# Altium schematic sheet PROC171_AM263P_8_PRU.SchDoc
size 431 x 279 mm; Date: Not shown in title block; ApprovedBy: Not shown in title block; CheckedBy: Not shown in title block; Author: Not shown in title block; CompanyName: Not shown in title block; Engineer: Not shown in title block; Organization: Not shown in title block; Address1: Not shown in title block; Address2: Not shown in title block; Address3: Not shown in title block; Address4: Not shown in title block; DocumentNumber: 12; Revision: Use project parameter SCH_Rev; SheetNumber: 12; SheetTotal: 26; PageSetup: Record=PageOptions¦CenterHorizontal=True¦CenterVertical=True¦PrintScale=1.00¦XCorrection=1.00¦YCorrection=1.00¦PrintKind=0¦BorderSize=5000000¦LeftOffset=0¦BottomOffset=0¦Orientation=2¦PaperLength=1000¦PaperWidth=1000¦Scale=100¦PaperSource=15¦PrintQuality=600¦MediaType=1¦DitherType=10¦PaperKind=Letter¦PrintScaleMode=1
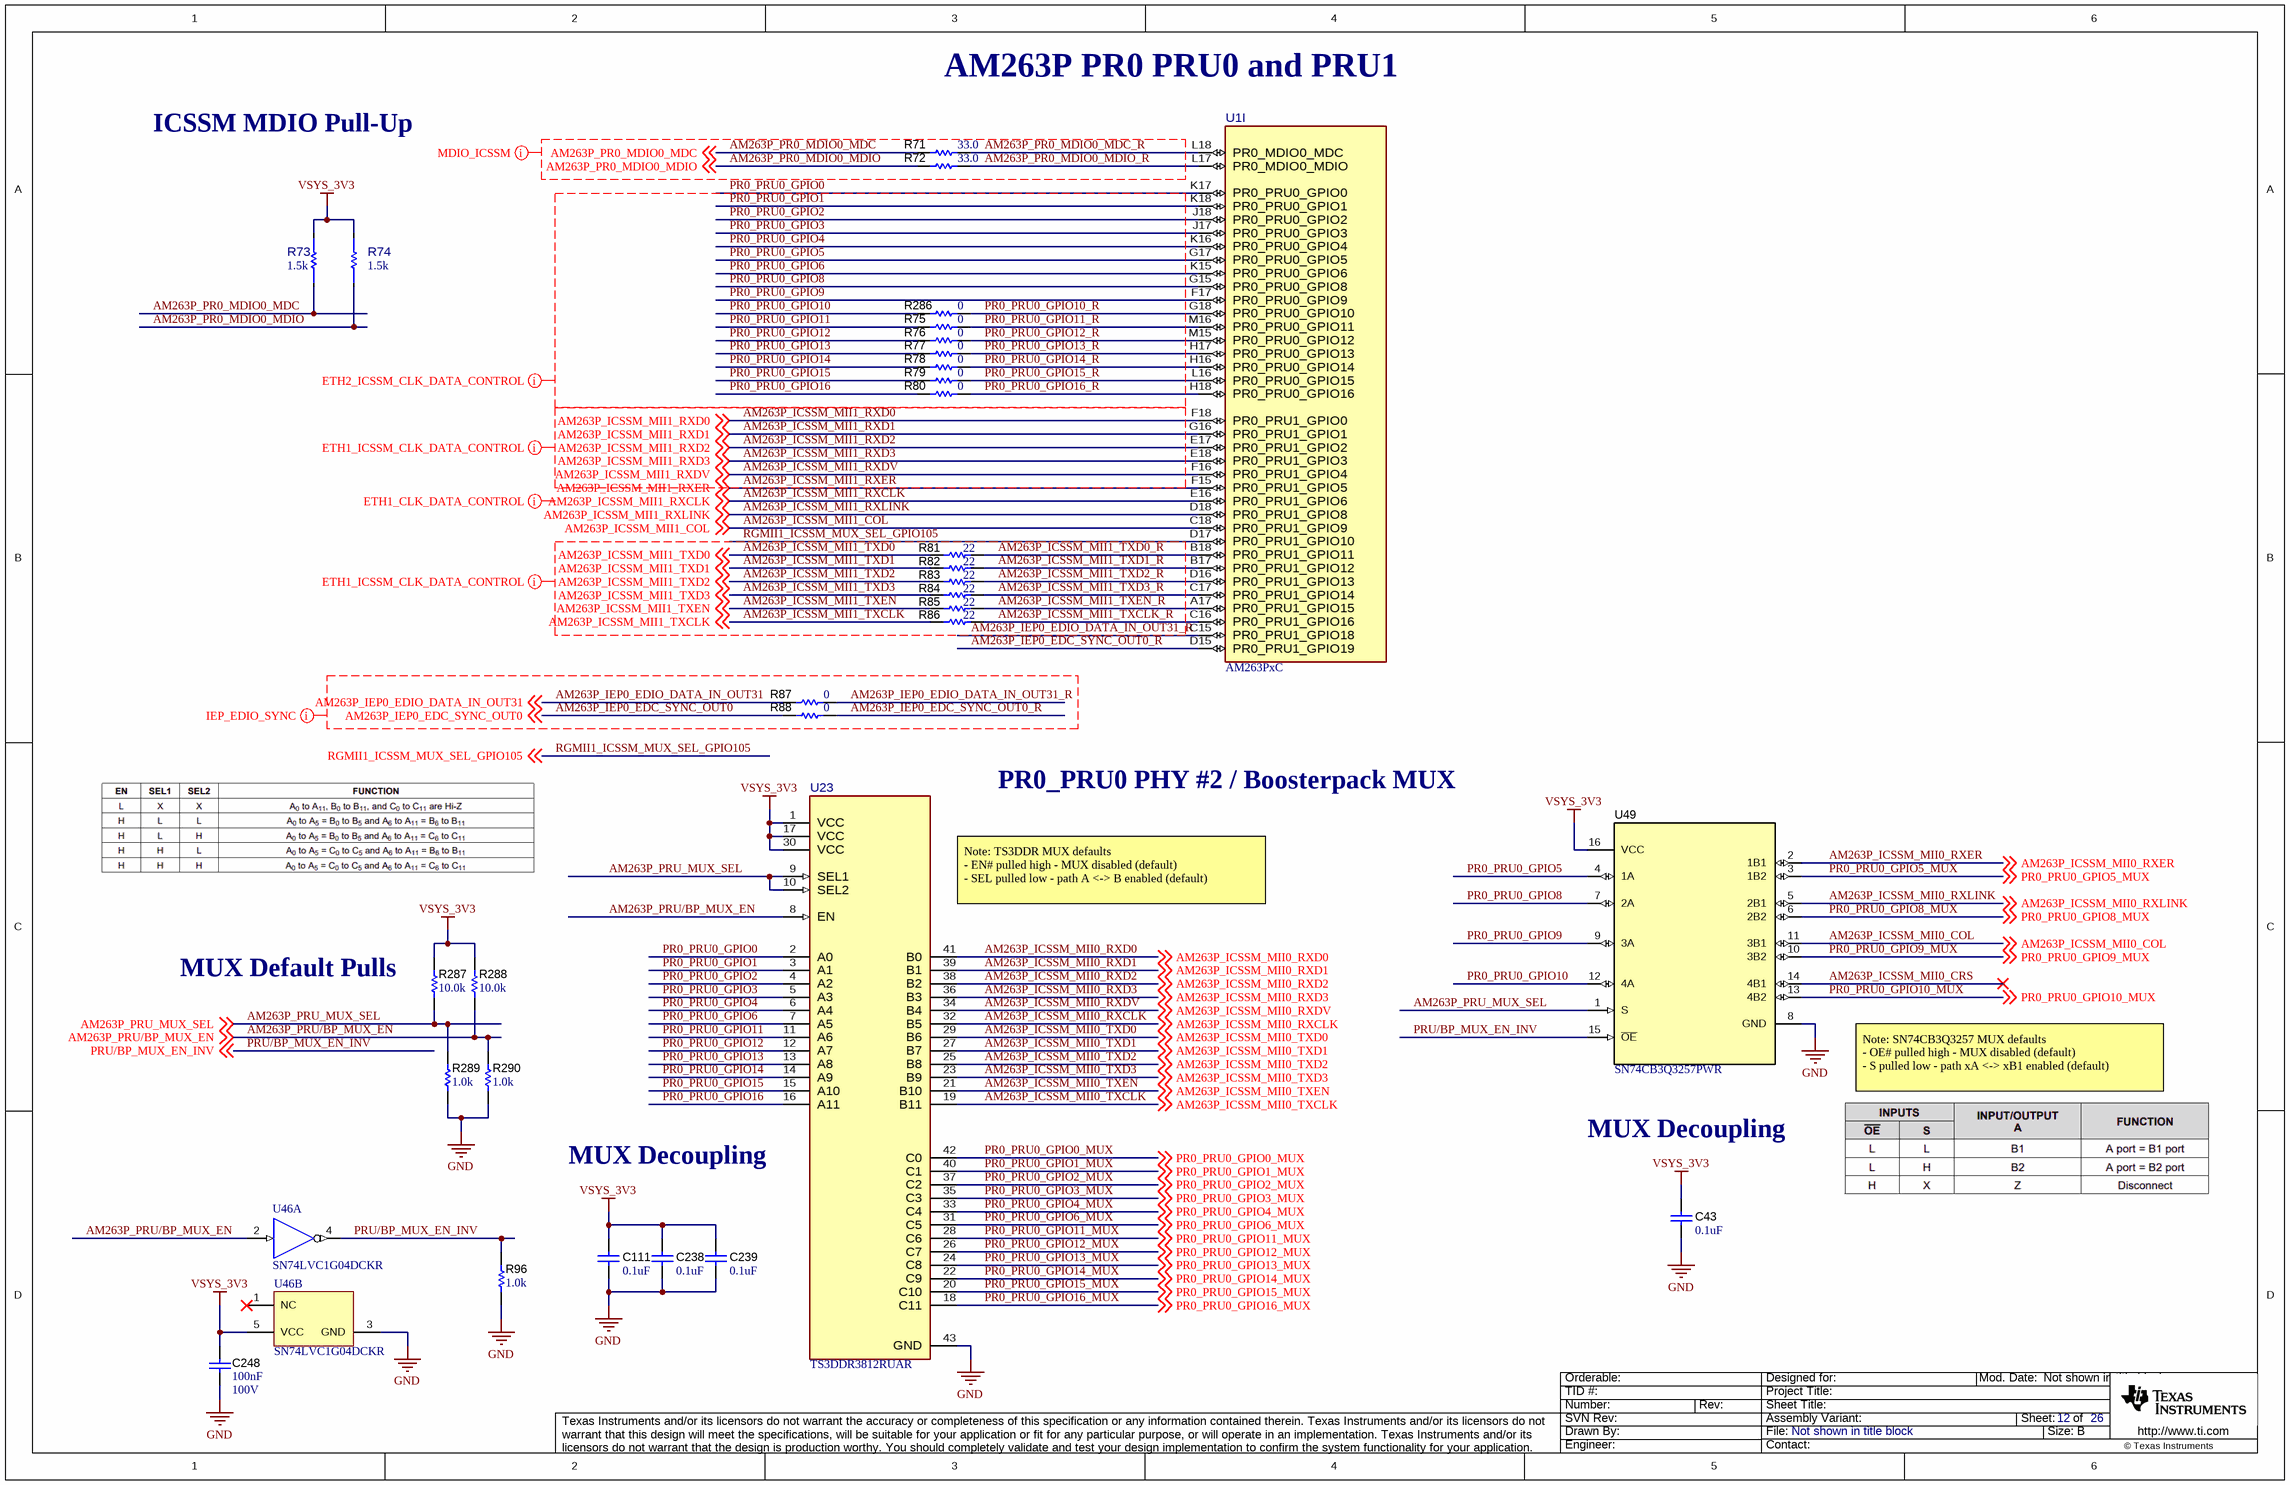
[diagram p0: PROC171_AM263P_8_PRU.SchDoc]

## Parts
C43  ValueDisplayed: 0.1uF  [0402]  (hidden comment: GRM155R71E104KE14D)
C111  ValueDisplayed: 0.1uF  [0402]  (hidden comment: GRM155R71E104KE14D)
C238  ValueDisplayed: 0.1uF  [0402]  (hidden comment: GRM155R71E104KE14D)
C239  ValueDisplayed: 0.1uF  [0402]  (hidden comment: GRM155R71E104KE14D)
C248  Cap_F: 100nF  VDC_V: 100V  [0603]  (hidden comment: GRM188R72A104KA35D)
R71  ValueDisplayed: 33.0  [0402L]  (hidden comment: ERJ-2RKF33R0X)
R72  ValueDisplayed: 33.0  [0402L]  (hidden comment: ERJ-2RKF33R0X)
R73  value 1.5k  [FP-ERJ-2GEJ152X_0402-MFG]  (hidden comment: ERJ-2GEJ152X)
R74  value 1.5k  [FP-ERJ-2GEJ152X_0402-MFG]  (hidden comment: ERJ-2GEJ152X)
R75  value 0  [0402L]  (hidden comment: ERJ-2GE0R00X)
R76  value 0  [0402L]  (hidden comment: ERJ-2GE0R00X)
R77  value 0  [0402L]  (hidden comment: ERJ-2GE0R00X)
R78  value 0  [0402L]  (hidden comment: ERJ-2GE0R00X)
R79  value 0  [0402L]  (hidden comment: ERJ-2GE0R00X)
R80  value 0  [0402L]  (hidden comment: ERJ-2GE0R00X)
R81  ValueDisplayed: 22  [0402]  (hidden comment: CRCW040222R0JNED)
R82  ValueDisplayed: 22  [0402]  (hidden comment: CRCW040222R0JNED)
R83  ValueDisplayed: 22  [0402]  (hidden comment: CRCW040222R0JNED)
R84  ValueDisplayed: 22  [0402]  (hidden comment: CRCW040222R0JNED)
R85  ValueDisplayed: 22  [0402]  (hidden comment: CRCW040222R0JNED)
R86  ValueDisplayed: 22  [0402]  (hidden comment: CRCW040222R0JNED)
R87  value 0  [0402L]  (hidden comment: ERJ-2GE0R00X)
R88  value 0  [0402L]  (hidden comment: ERJ-2GE0R00X)
R96  ValueDisplayed: 1.0k  [0402]  (hidden comment: ERJ-2GEJ102X)
R286  value 0  [0402L]  (hidden comment: ERJ-2GE0R00X)
R287  ValueDisplayed: 10.0k  [0402]  (hidden comment: ERJ-2RKF1002X)
R288  ValueDisplayed: 10.0k  [0402]  (hidden comment: ERJ-2RKF1002X)
R289  ValueDisplayed: 1.0k  [0402]  (hidden comment: ERJ-2GEJ102X)
R290  ValueDisplayed: 1.0k  [0402]  (hidden comment: ERJ-2GEJ102X)
U1  AM263PxC  [ZCZ0324A-MFG]  (part I of 13)
U23  TS3DDR3812RUAR  [RUA0042A-MFG]
U46  SN74LVC1G04DCKR  [DCK0005A_N]  (parts A,B of 2)
U49  SN74CB3Q3257PWR  [PW0016A_L]

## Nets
GND: C43.1 C111.1 C238.1 C239.1 C248.2 R96.1 R289.1 R290.1 U23.43(GND) U46.3(GND) U49.8(GND)
VSYS_3V3: C43.2 C111.2 C238.2 C239.2 C248.1 R73.2 R74.2 R287.1 R288.1 U23.1(VCC) U23.17(VCC) U23.30(VCC) U46.5(VCC) U49.16(VCC)
AM263P_ICSSM_MII0_COL: U49.11(3B1) ; off-sheet AM263P_ICSSM_MII0_COL
AM263P_ICSSM_MII0_CRS: U49.14(4B1)
AM263P_ICSSM_MII0_RXCLK: U23.32(B5) ; off-sheet AM263P_ICSSM_MII0_RXCLK
AM263P_ICSSM_MII0_RXD0: U23.41(B0) ; off-sheet AM263P_ICSSM_MII0_RXD0
AM263P_ICSSM_MII0_RXD1: U23.39(B1) ; off-sheet AM263P_ICSSM_MII0_RXD1
AM263P_ICSSM_MII0_RXD2: U23.38(B2) ; off-sheet AM263P_ICSSM_MII0_RXD2
AM263P_ICSSM_MII0_RXD3: U23.36(B3) ; off-sheet AM263P_ICSSM_MII0_RXD3
AM263P_ICSSM_MII0_RXDV: U23.34(B4) ; off-sheet AM263P_ICSSM_MII0_RXDV
AM263P_ICSSM_MII0_RXER: U49.2(1B1) ; off-sheet AM263P_ICSSM_MII0_RXER
AM263P_ICSSM_MII0_RXLINK: U49.5(2B1) ; off-sheet AM263P_ICSSM_MII0_RXLINK
AM263P_ICSSM_MII0_TXCLK: U23.19(B11) ; off-sheet AM263P_ICSSM_MII0_TXCLK
AM263P_ICSSM_MII0_TXD0: U23.29(B6) ; off-sheet AM263P_ICSSM_MII0_TXD0
AM263P_ICSSM_MII0_TXD1: U23.27(B7) ; off-sheet AM263P_ICSSM_MII0_TXD1
AM263P_ICSSM_MII0_TXD2: U23.25(B8) ; off-sheet AM263P_ICSSM_MII0_TXD2
AM263P_ICSSM_MII0_TXD3: U23.23(B9) ; off-sheet AM263P_ICSSM_MII0_TXD3
AM263P_ICSSM_MII0_TXEN: U23.21(B10) ; off-sheet AM263P_ICSSM_MII0_TXEN
AM263P_ICSSM_MII1_COL: U1.C18(PR0_PRU1_GPIO9) ; off-sheet AM263P_ICSSM_MII1_COL
AM263P_ICSSM_MII1_RXCLK: U1.E16(PR0_PRU1_GPIO6) ; off-sheet AM263P_ICSSM_MII1_RXCLK
AM263P_ICSSM_MII1_RXD0: U1.F18(PR0_PRU1_GPIO0) ; off-sheet AM263P_ICSSM_MII1_RXD0
AM263P_ICSSM_MII1_RXD1: U1.G16(PR0_PRU1_GPIO1) ; off-sheet AM263P_ICSSM_MII1_RXD1
AM263P_ICSSM_MII1_RXD2: U1.E17(PR0_PRU1_GPIO2) ; off-sheet AM263P_ICSSM_MII1_RXD2
AM263P_ICSSM_MII1_RXD3: U1.E18(PR0_PRU1_GPIO3) ; off-sheet AM263P_ICSSM_MII1_RXD3
AM263P_ICSSM_MII1_RXDV: U1.F16(PR0_PRU1_GPIO4) ; off-sheet AM263P_ICSSM_MII1_RXDV
AM263P_ICSSM_MII1_RXER: U1.F15(PR0_PRU1_GPIO5) ; off-sheet AM263P_ICSSM_MII1_RXER
AM263P_ICSSM_MII1_RXLINK: U1.D18(PR0_PRU1_GPIO8) ; off-sheet AM263P_ICSSM_MII1_RXLINK
AM263P_ICSSM_MII1_TXCLK: R86.1 ; off-sheet AM263P_ICSSM_MII1_TXCLK
AM263P_ICSSM_MII1_TXCLK_R: R86.2 U1.C16(PR0_PRU1_GPIO16)
AM263P_ICSSM_MII1_TXD0: R81.1 ; off-sheet AM263P_ICSSM_MII1_TXD0
AM263P_ICSSM_MII1_TXD0_R: R81.2 U1.B18(PR0_PRU1_GPIO11)
AM263P_ICSSM_MII1_TXD1: R82.1 ; off-sheet AM263P_ICSSM_MII1_TXD1
AM263P_ICSSM_MII1_TXD1_R: R82.2 U1.B17(PR0_PRU1_GPIO12)
AM263P_ICSSM_MII1_TXD2: R83.1 ; off-sheet AM263P_ICSSM_MII1_TXD2
AM263P_ICSSM_MII1_TXD2_R: R83.2 U1.D16(PR0_PRU1_GPIO13)
AM263P_ICSSM_MII1_TXD3: R84.1 ; off-sheet AM263P_ICSSM_MII1_TXD3
AM263P_ICSSM_MII1_TXD3_R: R84.2 U1.C17(PR0_PRU1_GPIO14)
AM263P_ICSSM_MII1_TXEN: R85.1 ; off-sheet AM263P_ICSSM_MII1_TXEN
AM263P_ICSSM_MII1_TXEN_R: R85.2 U1.A17(PR0_PRU1_GPIO15)
AM263P_IEP0_EDC_SYNC_OUT0: R88.1 ; off-sheet AM263P_IEP0_EDC_SYNC_OUT0
AM263P_IEP0_EDC_SYNC_OUT0_R: R88.2 U1.D15(PR0_PRU1_GPIO19)
AM263P_IEP0_EDIO_DATA_IN_OUT31: R87.1 ; off-sheet AM263P_IEP0_EDIO_DATA_IN_OUT31
AM263P_IEP0_EDIO_DATA_IN_OUT31_R: R87.2 U1.C15(PR0_PRU1_GPIO18)
AM263P_PR0_MDIO0_MDC: R71.1 R73.1 ; off-sheet AM263P_PR0_MDIO0_MDC
AM263P_PR0_MDIO0_MDC_R: R71.2 U1.L18(PR0_MDIO0_MDC)
AM263P_PR0_MDIO0_MDIO: R72.1 R74.1 ; off-sheet AM263P_PR0_MDIO0_MDIO
AM263P_PR0_MDIO0_MDIO_R: R72.2 U1.L17(PR0_MDIO0_MDIO)
AM263P_PRU/BP_MUX_EN: R288.2 R290.2 U23.8(EN) U46.2(A) ; off-sheet AM263P_PRU/BP_MUX_EN
AM263P_PRU_MUX_SEL: R287.2 R289.2 U23.9(SEL1) U23.10(SEL2) U49.1(S) ; off-sheet AM263P_PRU_MUX_SEL
PR0_PRU0_GPIO0: U1.K17(PR0_PRU0_GPIO0) U23.2(A0)
PR0_PRU0_GPIO0_MUX: U23.42(C0) ; off-sheet PR0_PRU0_GPIO0_MUX
PR0_PRU0_GPIO1: U1.K18(PR0_PRU0_GPIO1) U23.3(A1)
PR0_PRU0_GPIO1_MUX: U23.40(C1) ; off-sheet PR0_PRU0_GPIO1_MUX
PR0_PRU0_GPIO2: U1.J18(PR0_PRU0_GPIO2) U23.4(A2)
PR0_PRU0_GPIO2_MUX: U23.37(C2) ; off-sheet PR0_PRU0_GPIO2_MUX
PR0_PRU0_GPIO3: U1.J17(PR0_PRU0_GPIO3) U23.5(A3)
PR0_PRU0_GPIO3_MUX: U23.35(C3) ; off-sheet PR0_PRU0_GPIO3_MUX
PR0_PRU0_GPIO4: U1.K16(PR0_PRU0_GPIO4) U23.6(A4)
PR0_PRU0_GPIO4_MUX: U23.33(C4) ; off-sheet PR0_PRU0_GPIO4_MUX
PR0_PRU0_GPIO5: U1.G17(PR0_PRU0_GPIO5) U49.4(1A)
PR0_PRU0_GPIO5_MUX: U49.3(1B2) ; off-sheet PR0_PRU0_GPIO5_MUX
PR0_PRU0_GPIO6: U1.K15(PR0_PRU0_GPIO6) U23.7(A5)
PR0_PRU0_GPIO6_MUX: U23.31(C5) ; off-sheet PR0_PRU0_GPIO6_MUX
PR0_PRU0_GPIO8: U1.G15(PR0_PRU0_GPIO8) U49.7(2A)
PR0_PRU0_GPIO8_MUX: U49.6(2B2) ; off-sheet PR0_PRU0_GPIO8_MUX
PR0_PRU0_GPIO9: U1.F17(PR0_PRU0_GPIO9) U49.9(3A)
PR0_PRU0_GPIO9_MUX: U49.10(3B2) ; off-sheet PR0_PRU0_GPIO9_MUX
PR0_PRU0_GPIO10: R286.1 U49.12(4A)
PR0_PRU0_GPIO10_MUX: U49.13(4B2) ; off-sheet PR0_PRU0_GPIO10_MUX
PR0_PRU0_GPIO10_R: R286.2 U1.G18(PR0_PRU0_GPIO10)
PR0_PRU0_GPIO11: R75.1 U23.11(A6)
PR0_PRU0_GPIO11_MUX: U23.28(C6) ; off-sheet PR0_PRU0_GPIO11_MUX
PR0_PRU0_GPIO11_R: R75.2 U1.M16(PR0_PRU0_GPIO11)
PR0_PRU0_GPIO12: R76.1 U23.12(A7)
PR0_PRU0_GPIO12_MUX: U23.26(C7) ; off-sheet PR0_PRU0_GPIO12_MUX
PR0_PRU0_GPIO12_R: R76.2 U1.M15(PR0_PRU0_GPIO12)
PR0_PRU0_GPIO13: R77.1 U23.13(A8)
PR0_PRU0_GPIO13_MUX: U23.24(C8) ; off-sheet PR0_PRU0_GPIO13_MUX
PR0_PRU0_GPIO13_R: R77.2 U1.H17(PR0_PRU0_GPIO13)
PR0_PRU0_GPIO14: R78.1 U23.14(A9)
PR0_PRU0_GPIO14_MUX: U23.22(C9) ; off-sheet PR0_PRU0_GPIO14_MUX
PR0_PRU0_GPIO14_R: R78.2 U1.H16(PR0_PRU0_GPIO14)
PR0_PRU0_GPIO15: R79.1 U23.15(A10)
PR0_PRU0_GPIO15_MUX: U23.20(C10) ; off-sheet PR0_PRU0_GPIO15_MUX
PR0_PRU0_GPIO15_R: R79.2 U1.L16(PR0_PRU0_GPIO15)
PR0_PRU0_GPIO16: R80.1 U23.16(A11)
PR0_PRU0_GPIO16_MUX: U23.18(C11) ; off-sheet PR0_PRU0_GPIO16_MUX
PR0_PRU0_GPIO16_R: R80.2 U1.H18(PR0_PRU0_GPIO16)
PRU/BP_MUX_EN_INV: R96.2 U46.4(Y) U49.15(~{OE}) ; off-sheet PRU/BP_MUX_EN_INV
RGMII1_ICSSM_MUX_SEL_GPIO105: U1.D17(PR0_PRU1_GPIO10) ; off-sheet RGMII1_ICSSM_MUX_SEL_GPIO105

Not connected (* = marked no-connect by the designer): U46 1(NC)*

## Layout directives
mark named IEP_EDIO_SYNC: AM263P_IEP0_EDC_SYNC_OUT0, AM263P_IEP0_EDC_SYNC_OUT0_R, AM263P_IEP0_EDIO_DATA_IN_OUT31, AM263P_IEP0_EDIO_DATA_IN_OUT31_R
mark named ETH2_ICSSM_CLK_DATA_CONTROL: PR0_PRU0_GPIO0, PR0_PRU0_GPIO1, PR0_PRU0_GPIO2, PR0_PRU0_GPIO3, PR0_PRU0_GPIO4, PR0_PRU0_GPIO5, PR0_PRU0_GPIO6, PR0_PRU0_GPIO8, PR0_PRU0_GPIO9, PR0_PRU0_GPIO10, PR0_PRU0_GPIO10_R, PR0_PRU0_GPIO11, PR0_PRU0_GPIO11_R, PR0_PRU0_GPIO12, PR0_PRU0_GPIO12_R, PR0_PRU0_GPIO13, PR0_PRU0_GPIO13_R, PR0_PRU0_GPIO14, PR0_PRU0_GPIO14_R, PR0_PRU0_GPIO15, PR0_PRU0_GPIO15_R, PR0_PRU0_GPIO16, PR0_PRU0_GPIO16_R
mark named ETH1_ICSSM_CLK_DATA_CONTROL: AM263P_ICSSM_MII1_RXD0, AM263P_ICSSM_MII1_RXD1, AM263P_ICSSM_MII1_RXD2, AM263P_ICSSM_MII1_RXD3, AM263P_ICSSM_MII1_RXDV, AM263P_ICSSM_MII1_RXER, AM263P_ICSSM_MII1_TXCLK, AM263P_ICSSM_MII1_TXCLK_R, AM263P_ICSSM_MII1_TXD0, AM263P_ICSSM_MII1_TXD0_R, AM263P_ICSSM_MII1_TXD1, AM263P_ICSSM_MII1_TXD1_R, AM263P_ICSSM_MII1_TXD2, AM263P_ICSSM_MII1_TXD2_R, AM263P_ICSSM_MII1_TXD3, AM263P_ICSSM_MII1_TXD3_R, AM263P_ICSSM_MII1_TXEN, AM263P_ICSSM_MII1_TXEN_R, AM263P_IEP0_EDIO_DATA_IN_OUT31_R, RGMII1_ICSSM_MUX_SEL_GPIO105
mark named MDIO_ICSSM: AM263P_PR0_MDIO0_MDC, AM263P_PR0_MDIO0_MDC_R, AM263P_PR0_MDIO0_MDIO, AM263P_PR0_MDIO0_MDIO_R
mark named ETH1_CLK_DATA_CONTROL: (no net found under the mark)

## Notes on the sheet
- AM263P PR0 PRU0 and PRU1
- ICSSM MDIO Pull-Up
- PR0_PRU0 PHY #2 / Boosterpack MUX
- (near U23) Note: TS3DDR MUX defaults
  - EN# pulled high - MUX disabled (default)
  - SEL pulled low - path A <-> B enabled (default)
- (near R287) MUX Default Pulls
- Note: SN74CB3Q3257 MUX defaults
  - OE# pulled high - MUX disabled (default)
  - S pulled low - path xA <-> xB1 enabled (default)
- MUX Decoupling

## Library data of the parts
C43 C111 C238 C239 = CMP-0006659-2: CAP, CERM, 0.1 uF, 25 V, +/- 10%, X7R, 0402; Manufacturer: MuRata; TaMin_C: -55°C; Polarized: N; SizeAreaWB_mm2: 3; U/M: EA; Value: 0.1uF; TaMax_C: 125°C; SizeZ_mm: 0.6; SizeX_mm: 1; SizeY_mm: 0.5; Value2: 25V; Cap_F: 100nF; AEC Category: Q200; Value1: Unknown
C248 = CMP-0007469-4: CAP, CERM, 0.1 uF, 100 V, +/- 10%, X7R, 0603; Manufacturer: MuRata; TaMin_C: -55°C; Polarized: N; SizeAreaWB_mm2: 4.68; Value1: Unknown; U/M: EA; Value: 0.1uF; TaMax_C: 125°C; SizeZ_mm: 1; SizeX_mm: 1.6; SizeY_mm: 0.8; SizeArea_mm2: 1.28; AEC Category: Q200
R71 R72 = CMP-0026696-1: RES, 33.0, 1%, 0.1 W, 0402; Manufacturer: Panasonic; Power_W: 100mW; TempCo: 100 ppm/C; Value_Code: 33R0; U/M: EA; Value: 33.0; Res_ohm: 33; SizeX_mm: 1; SizeY_mm: 0.5; SizeZ_mm: 0.6; Value2: 0.1W; VDC_V: 50V; AEC Category: Q200
R73 R74 = CMP-0042990-1: Res Thick Film 0402 1.5K Ohm 5% 1/10W ±200ppm/°C Molded SMD Punched Carrier T/R; Manufacturer: Panasonic; AEC Grade: Grade 0; AEC Qualified: Yes; Power_W: 100mW; SizeZ_mm: 0.4mm; VDC_V: 50V; Category 5A00970A6D5C81C7: Uncategorized; Category 5C6A91606D4187Ad: Resistors; Category 7542B8484461Ae85: Passive Components; Category Cd01000Bfc2916C6: Single Components
R75-R80 R87 R88 R286 = CMP-0026992-3: RES, 0, 5%, 0.1 W, AEC-Q200 Grade 0, 0402; Manufacturer: Panasonic; Power_W: 100mW; TempCo: 600 ppm/C; Value_Code: 0000; EIA_Code: E24; SizeX_mm: 1; SizeY_mm: 0.5; SizeZ_mm: 0.6; Value2: 0.1W; AEC Qualified: Y; VDC_V: 50V; AEC Category: Q200; SizeAreaWB_mm2: 3
R81-R86 = CMP-0026880-3: RES, 22, 5%, 0.063 W, AEC-Q200 Grade 0, 0402; Manufacturer: Vishay-Dale; Power_W: 63mW; TempCo: 200 ppm/C; Value_Code: 22R0; Value: 22; EIA_Code: E24; SizeX_mm: 1; SizeY_mm: 0.5; SizeZ_mm: 0.6; Value2: 0.063W; AEC Qualified: Y; VDC_V: 50V; AEC Category: Q200; AEC Grade: 0
R96 R289 R290 = CMP-0078193-1: RES, 1.0 k, 5%, 0.1 W, AEC-Q200 Grade 0, 0402; Manufacturer: Panasonic; Value_Code: 1k00; SizeArea_mm2: 0.5; AEC Qualified: Y; AEC Category: Q200; Res_ohm: 1k; Value: 1.0k; SizeZ_mm: 0.6; Green_REACh: Passed; EIA_Code: E24; TempCo: 200 ppm/C; AEC Grade: 0; Power_W: 100mW; VDC_V: 50V; Value2: 0.1W; Green_Lifecycle: Active; U/M: EA; SizeX_mm: 1
R287 R288 = CMP-0026658-1: RES, 10.0 k, 1%, 0.1 W, 0402; Manufacturer: Panasonic; Power_W: 100mW; TempCo: 100 ppm/C; Value_Code: 10k0; U/M: EA; Value: 10.0k; EIA_Code: E96; Res_ohm: 10k; SizeX_mm: 1; SizeY_mm: 0.5; SizeZ_mm: 0.6; Value2: 0.1W; VDC_V: 50V; AEC Category: Q200
U1 = CMP-0001698-2: Sitara™ Microcontroller; Manufacturer: Texas Instruments; SizeZ_mm: 1.4mm; Core Architecture: ARM Cortex-R5F; Data Bus Width: 32bits; Frequency_Fixed: 200MHz; Interface: I2C,SPI,UART,CAN,LIN,Ethernet,Other; Max Supply Voltage: 3.465V; Memory Size: 2MBytes; Memory Type: RAM; Min Supply Voltage: 1.14V; Number Of Cores: 1; Number Of I/Os: 140; Number Of I2C Channels: 4; Number Of Spi Channels: 5; Number Of Uart Channels: 6; Standoff Height: 0.35mm; AEC Category: Q200; CompType: IC
U23 = CMP-0093539-2: IC MUX/DEMUX DDR3 1:2 42WQFN; Manufacturer: Texas Instruments; TaMax_C: +85°C; TaMin_C: -40°C; On State Resistance: 8Ω; SizeZ_mm: 0.8mm; Min Supply Voltage: 3V; Standoff Height: 0mm; Max Supply Voltage: 3.6V; AEC Qualified: No; PositionCount: 12; -3Db Bandwith: 1.675GHz; Nominal Supply Current: 300uA; AEC Category: Q200
U46 = CMP-0051684-3: Single Inverter, DCK0005A, LARGE T&R; Manufacturer: Texas Instruments; Input Type: CMOS/TTL; Output Drive (IOL/IOH)(Max)(mA): 32/-32; Sub-Family: Inverting Buffer/Driver; VCC(Min)(V): 1.65; Bits(#): 1; Schmitt Trigger: No; Technology Family: LVC; Rating: Catalog; ICC @ Nom Voltage(Max)(mA): 0.01; tpd @ Nom Voltage(Max)(ns): 7.5,5.2,4.2,3.7; Voltage(Nom)(V): 1.8,2.5,3.3,5; F @ Nom Voltage(Max)(Mhz): 150; Output Type: CMOS; VCC(Max)(V): 5.5; Logic: Inverting; AEC Category: Q200; AEC Qualified: N; CompType: IC; SizeAreaWB_mm2: 9.3; SizeArea_mm2: 4.2; SizeX_mm: 2.1; SizeY_mm: 2.0; SizeZ_mm: 1.1
U49 = CMP-0076540-1: 4-Bit One-of-2 FET Multiplexer/Demultiplexer 2.5-V/3.3-V Low-Voltage, High-Bandwidth Bus Switch, PW0016A (TSSOP-16); Manufacturer: Texas Instruments; SizeAreaWB_mm2: 58.8; SizeArea_mm2: 32.0; SizeZ_mm: 1.2; SizeY_mm: 5.0; U/M: EA; CompType: IC; SizeX_mm: 6.4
